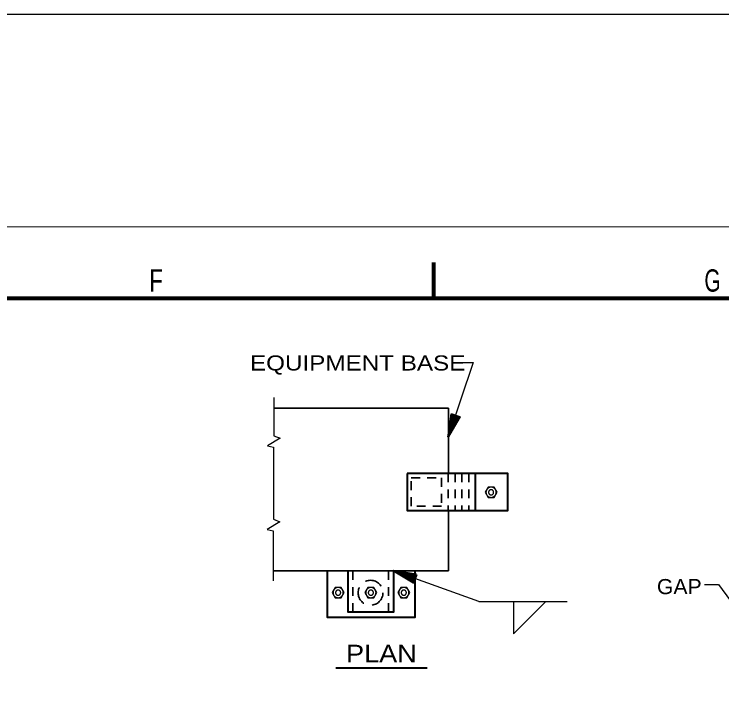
# Model space of a CAD drawing. Extents: x 55 to 190, y 198 to 264.
# Drawn here: x 114.24 to 126.14, y 249.95 to 261.43 of the extents above; entities that cross this region are included whole.
import ezdxf
from ezdxf.enums import TextEntityAlignment as Align

# ---------------------------------------------------------------- set-up
doc = ezdxf.new("R2010")
doc.units = 0
doc.header["$LTSCALE"] = 0.1
doc.linetypes.add('MEDIUM_DASHED', pattern=[4.5, 3, -1.5])
doc.linetypes.add('SHORT_DASHED', pattern=[2.7, 1.5, -1.2])
for name, color, linetype, lineweight in [('1', 7, 'Continuous', 25), ('2', 7, 'Continuous', 40), ('3', 7, 'Continuous', 25)]:
    doc.layers.add(name, color=color, linetype=linetype, lineweight=lineweight)

msp = doc.modelspace()

# ---------------------------------------------------------------- linework, layer by layer
at = {"layer": '1', "lineweight": 80}
msp.add_line((121.2927, 257.2525), (121.2927, 256.6525), dxfattribs=at)
at = {"layer": '1', "lineweight": 13}
msp.add_lwpolyline([(62.4915, 257.8525), (146.5927, 257.8525), (146.5927, 198.4512), (62.4915, 198.4512)], close=True, dxfattribs=at)
at = {"layer": '1', "lineweight": 80}
msp.add_lwpolyline([(65.1915, 256.6525), (145.3927, 256.6525), (145.3927, 199.6512), (65.1915, 199.6512)], close=True, dxfattribs=at)
at = {"layer": '2'}
for p, q in [((121.5389, 254.3221), (121.6058, 254.7029)), ((121.5389, 254.3221), (121.6265, 254.6965)), ((121.5389, 254.3221), (121.6424, 254.6907)), ((121.6593, 254.6854), (121.5389, 254.3221)), ((121.5389, 254.3221), (121.6775, 254.6791)), ((121.5389, 254.3221), (121.7127, 254.6672)), ((121.9919, 253.7091), (121.9919, 253.0871)), ((120.9806, 251.9388), (120.6203, 252.0671)), ((120.6203, 252.0671), (120.9928, 251.9713)), ((120.6203, 252.0671), (120.9616, 251.8856)), ((120.6203, 252.0671), (120.974, 251.9208)), ((120.6203, 252.0671), (120.9865, 251.9554)), ((120.6203, 252.0671), (120.9994, 251.9917)), ((119.6463, 250.437), (121.182, 250.437))]:
    msp.add_line(p, q, dxfattribs=at)
at = {"layer": '2', "linetype": 'SHORT_DASHED', "lineweight": 35}
for p, q in [((121.5381, 253.7091), (121.5381, 253.0871)), ((121.6535, 253.7091), (121.6535, 253.0871)), ((121.7686, 253.7091), (121.7686, 253.0871)), ((121.8874, 253.7091), (121.8874, 253.0871)), ((119.9369, 252.0671), (119.9369, 251.3739)), ((120.5351, 252.0671), (120.5351, 251.3739))]:
    msp.add_line(p, q, dxfattribs=at)
at = {"layer": '2', "lineweight": 35}
for p in [(121.5418, 253.0881), (118.6002, 252.0676)]:
    msp.add_line(p, (121.5418, 252.0676), dxfattribs=at)
at = {"layer": '2', "lineweight": 25}
for q in [(120.6203, 252.0671), (123.5423, 251.5533)]:
    msp.add_line((122.0562, 251.5533), q, dxfattribs=at)
for points in [[(121.6971, 255.5747), (121.9561, 255.5747), (121.5389, 254.3221)], [(118.6071, 254.9844), (118.6071, 254.3428), (118.7139, 254.2999), (118.4999, 254.1713), (118.5999, 254.1499), (118.5999, 253.4646)], [(118.5999, 253.4646), (118.5999, 252.9365), (118.7068, 252.8936), (118.4928, 252.765), (118.5928, 252.7436), (118.5928, 251.9038)], [(125.8499, 251.8406), (126.0854, 251.8406), (127.0143, 250.5714)], [(122.6385, 251.5533), (122.6385, 251.0109), (123.1809, 251.5533)]]:
    msp.add_lwpolyline(points, dxfattribs=at)
at = {"layer": '2', "lineweight": 35}
msp.add_lwpolyline([(118.6068, 254.8042), (121.5418, 254.8042), (121.5418, 253.7056)], dxfattribs=at)
at = {"layer": '2'}
for points in [[(121.5873, 254.709), (121.7326, 254.6603), (121.5389, 254.3221)], [(121.5873, 254.709), (121.5389, 254.3221), (121.6955, 254.6732)], [(119.5008, 252.0663), (119.5008, 251.2929), (120.9828, 251.2929), (120.9828, 252.0663)], [(120.6203, 252.0671), (120.6203, 251.3739), (119.854, 251.3739), (119.854, 252.0671)], [(121.006, 252.0099), (120.9542, 251.866), (120.6203, 252.0671)], [(121.006, 252.0099), (120.6203, 252.0671), (120.9679, 251.9028)]]:
    msp.add_lwpolyline(points, dxfattribs=at)
msp.add_lwpolyline([(120.8497, 253.7091), (120.8497, 253.0871), (122.5411, 253.0871), (122.5411, 253.7091)], close=True, dxfattribs=at)
at = {"layer": '2', "linetype": 'SHORT_DASHED', "lineweight": 35}
msp.add_lwpolyline([(121.4283, 253.6337), (121.4283, 253.158), (120.915, 253.158), (120.915, 253.6337)], close=True, dxfattribs=at)
at = {"layer": '2', "lineweight": 25}
for points in [[(122.3607, 253.3913), (122.3102, 253.4786), (122.2096, 253.4786), (122.1593, 253.3913), (122.2096, 253.3048), (122.3102, 253.3048)], [(122.3451, 253.3807), (122.3464, 253.3969), (122.3451, 253.4019), (122.3445, 253.4077), (122.3438, 253.413), (122.3419, 253.4183), (122.3403, 253.4231), (122.3382, 253.4281), (122.3358, 253.4329), (122.3327, 253.4379), (122.3297, 253.4419), (122.3263, 253.4464), (122.3229, 253.4503), (122.3189, 253.454), (122.3152, 253.458), (122.3104, 253.4612), (122.3065, 253.4644), (122.3017, 253.4673), (122.2967, 253.4694), (122.2916, 253.4715), (122.2864, 253.4734), (122.2816, 253.4752), (122.2758, 253.476), (122.2707, 253.4768), (122.2652, 253.4776), (122.2599, 253.4776), (122.2546, 253.4776), (122.2493, 253.4768), (122.2438, 253.476), (122.2382, 253.4752), (122.2334, 253.4734), (122.2284, 253.4715), (122.2231, 253.4694), (122.2184, 253.4673), (122.2139, 253.4644), (122.2096, 253.4612), (122.2049, 253.458), (122.2014, 253.454), (122.1972, 253.4503), (122.1935, 253.4464), (122.19, 253.4419), (122.1874, 253.4379), (122.1845, 253.4329), (122.1816, 253.4281), (122.1795, 253.4231), (122.1781, 253.4183), (122.1763, 253.413), (122.1755, 253.4077), (122.1747, 253.4019), (122.1739, 253.3969), (122.1739, 253.3913), (122.1739, 253.3863), (122.1747, 253.3807), (122.1755, 253.3752), (122.1763, 253.3699), (122.1781, 253.3649), (122.1795, 253.3598), (122.1816, 253.3548), (122.1845, 253.3495), (122.1874, 253.3453), (122.19, 253.3408), (122.1935, 253.3365), (122.1972, 253.3329), (122.2014, 253.3286), (122.2049, 253.3249), (122.2096, 253.3217), (122.2139, 253.3188), (122.2184, 253.3159), (122.2231, 253.3135), (122.2284, 253.3112), (122.2334, 253.3096), (122.2382, 253.3077), (122.2438, 253.3069), (122.2493, 253.3056), (122.2546, 253.3053), (122.2599, 253.3053), (122.2652, 253.3053), (122.2707, 253.3056), (122.2758, 253.3069), (122.2816, 253.3077), (122.2864, 253.3096), (122.2916, 253.3112), (122.2967, 253.3135), (122.3017, 253.3159), (122.3065, 253.3188), (122.3104, 253.3217), (122.3152, 253.3249), (122.3189, 253.3286), (122.3229, 253.3329), (122.3263, 253.3365), (122.3297, 253.3408), (122.3327, 253.3453), (122.3358, 253.3495), (122.3382, 253.3548), (122.3403, 253.3598), (122.3419, 253.3649), (122.3438, 253.3699), (122.3445, 253.3752)], [(122.3028, 253.3845), (122.303, 253.3929), (122.3028, 253.3956), (122.302, 253.3982), (122.3017, 253.4011), (122.3009, 253.4035), (122.3001, 253.4061), (122.2991, 253.4085), (122.298, 253.4106), (122.2961, 253.4136), (122.2948, 253.4157), (122.2932, 253.4178), (122.2914, 253.4202), (122.2895, 253.4212), (122.2874, 253.4236), (122.2856, 253.4252), (122.2834, 253.4265), (122.2808, 253.4281), (122.2782, 253.4292), (122.2755, 253.4305), (122.2734, 253.431), (122.2707, 253.4318), (122.2684, 253.4326), (122.2652, 253.4329), (122.2628, 253.4331), (122.2599, 253.4331), (122.2572, 253.4331), (122.2543, 253.4329), (122.2519, 253.4326), (122.2488, 253.4318), (122.2461, 253.431), (122.2438, 253.4305), (122.2416, 253.4292), (122.239, 253.4281), (122.2369, 253.4265), (122.2348, 253.4252), (122.2318, 253.4236), (122.2305, 253.4212), (122.2284, 253.4202), (122.2266, 253.4178), (122.225, 253.4157), (122.2231, 253.4136), (122.2223, 253.4106), (122.2207, 253.4085), (122.2194, 253.4061), (122.2189, 253.4035), (122.2178, 253.4011), (122.2173, 253.3982), (122.217, 253.3956), (122.2165, 253.3929), (122.2165, 253.3897), (122.2165, 253.3874), (122.217, 253.3845), (122.2173, 253.3823), (122.2178, 253.3789), (122.2189, 253.3768), (122.2194, 253.3741), (122.2207, 253.3718), (122.2223, 253.3688), (122.2231, 253.3667), (122.225, 253.3649), (122.2266, 253.3625), (122.2284, 253.3606), (122.2305, 253.3583), (122.2318, 253.3572), (122.2348, 253.3553), (122.2369, 253.3538), (122.239, 253.3522), (122.2416, 253.3511), (122.2438, 253.3495), (122.2461, 253.349), (122.2488, 253.3479), (122.2519, 253.3477), (122.2543, 253.3474), (122.2572, 253.3469), (122.2599, 253.3469), (122.2628, 253.3469), (122.2652, 253.3474), (122.2684, 253.3477), (122.2707, 253.3479), (122.2734, 253.349), (122.2755, 253.3495), (122.2782, 253.3511), (122.2808, 253.3522), (122.2834, 253.3538), (122.2856, 253.3553), (122.2874, 253.3572), (122.2895, 253.3583), (122.2914, 253.3606), (122.2932, 253.3625), (122.2948, 253.3649), (122.2961, 253.3667), (122.298, 253.3688), (122.2991, 253.3718), (122.3001, 253.3741), (122.3009, 253.3768), (122.3017, 253.3789), (122.302, 253.3823)], [(119.7876, 251.7036), (119.7371, 251.7909), (119.6366, 251.7909), (119.5863, 251.7036), (119.6366, 251.617), (119.7371, 251.617)], [(119.772, 251.693), (119.7733, 251.7091), (119.772, 251.7141), (119.7715, 251.72), (119.7707, 251.7252), (119.7688, 251.7305), (119.7673, 251.7353), (119.7651, 251.7403), (119.7627, 251.7451), (119.7596, 251.7501), (119.7567, 251.7541), (119.7532, 251.7586), (119.7498, 251.7626), (119.7458, 251.7663), (119.7421, 251.7702), (119.7374, 251.7734), (119.7334, 251.7766), (119.7286, 251.7795), (119.7236, 251.7816), (119.7186, 251.7837), (119.7133, 251.7856), (119.7085, 251.7874), (119.7027, 251.7882), (119.6977, 251.789), (119.6921, 251.7898), (119.6868, 251.7898), (119.6815, 251.7898), (119.6762, 251.789), (119.6707, 251.7882), (119.6651, 251.7874), (119.6604, 251.7856), (119.6553, 251.7837), (119.65, 251.7816), (119.6453, 251.7795), (119.6408, 251.7766), (119.6366, 251.7734), (119.6318, 251.7702), (119.6283, 251.7663), (119.6241, 251.7626), (119.6204, 251.7586), (119.617, 251.7541), (119.6143, 251.7501), (119.6114, 251.7451), (119.6085, 251.7403), (119.6064, 251.7353), (119.6051, 251.7305), (119.6032, 251.7252), (119.6024, 251.72), (119.6016, 251.7141), (119.6008, 251.7091), (119.6008, 251.7036), (119.6008, 251.6985), (119.6016, 251.693), (119.6024, 251.6874), (119.6032, 251.6821), (119.6051, 251.6771), (119.6064, 251.6721), (119.6085, 251.667), (119.6114, 251.6617), (119.6143, 251.6575), (119.617, 251.653), (119.6204, 251.6488), (119.6241, 251.6451), (119.6283, 251.6408), (119.6318, 251.6371), (119.6366, 251.634), (119.6408, 251.631), (119.6453, 251.6281), (119.65, 251.6258), (119.6553, 251.6234), (119.6604, 251.6218), (119.6651, 251.6199), (119.6707, 251.6192), (119.6762, 251.6178), (119.6815, 251.6176), (119.6868, 251.6176), (119.6921, 251.6176), (119.6977, 251.6178), (119.7027, 251.6192), (119.7085, 251.6199), (119.7133, 251.6218), (119.7186, 251.6234), (119.7236, 251.6258), (119.7286, 251.6281), (119.7334, 251.631), (119.7374, 251.634), (119.7421, 251.6371), (119.7458, 251.6408), (119.7498, 251.6451), (119.7532, 251.6488), (119.7567, 251.653), (119.7596, 251.6575), (119.7627, 251.6617), (119.7651, 251.667), (119.7673, 251.6721), (119.7688, 251.6771), (119.7707, 251.6821), (119.7715, 251.6874)], [(120.3382, 251.7036), (120.2877, 251.7909), (120.1871, 251.7909), (120.1369, 251.7036), (120.1871, 251.617), (120.2877, 251.617)], [(120.3226, 251.693), (120.3239, 251.7091), (120.3226, 251.7141), (120.3221, 251.72), (120.3213, 251.7252), (120.3194, 251.7305), (120.3179, 251.7353), (120.3157, 251.7403), (120.3134, 251.7451), (120.3102, 251.7501), (120.3073, 251.7541), (120.3038, 251.7586), (120.3004, 251.7626), (120.2964, 251.7663), (120.2927, 251.7702), (120.2879, 251.7734), (120.284, 251.7766), (120.2792, 251.7795), (120.2742, 251.7816), (120.2692, 251.7837), (120.2639, 251.7856), (120.2591, 251.7874), (120.2533, 251.7882), (120.2483, 251.789), (120.2427, 251.7898), (120.2374, 251.7898), (120.2321, 251.7898), (120.2268, 251.789), (120.2213, 251.7882), (120.2157, 251.7874), (120.211, 251.7856), (120.2059, 251.7837), (120.2006, 251.7816), (120.1959, 251.7795), (120.1914, 251.7766), (120.1871, 251.7734), (120.1824, 251.7702), (120.1789, 251.7663), (120.1747, 251.7626), (120.171, 251.7586), (120.1676, 251.7541), (120.1649, 251.7501), (120.162, 251.7451), (120.1591, 251.7403), (120.157, 251.7353), (120.1557, 251.7305), (120.1538, 251.7252), (120.153, 251.72), (120.1522, 251.7141), (120.1514, 251.7091), (120.1514, 251.7036), (120.1514, 251.6985), (120.1522, 251.693), (120.153, 251.6874), (120.1538, 251.6821), (120.1557, 251.6771), (120.157, 251.6721), (120.1591, 251.667), (120.162, 251.6617), (120.1649, 251.6575), (120.1676, 251.653), (120.171, 251.6488), (120.1747, 251.6451), (120.1789, 251.6408), (120.1824, 251.6371), (120.1871, 251.634), (120.1914, 251.631), (120.1959, 251.6281), (120.2006, 251.6258), (120.2059, 251.6234), (120.211, 251.6218), (120.2157, 251.6199), (120.2213, 251.6192), (120.2268, 251.6178), (120.2321, 251.6176), (120.2374, 251.6176), (120.2427, 251.6176), (120.2483, 251.6178), (120.2533, 251.6192), (120.2591, 251.6199), (120.2639, 251.6218), (120.2692, 251.6234), (120.2742, 251.6258), (120.2792, 251.6281), (120.284, 251.631), (120.2879, 251.634), (120.2927, 251.6371), (120.2964, 251.6408), (120.3004, 251.6451), (120.3038, 251.6488), (120.3073, 251.653), (120.3102, 251.6575), (120.3134, 251.6617), (120.3157, 251.667), (120.3179, 251.6721), (120.3194, 251.6771), (120.3213, 251.6821), (120.3221, 251.6874)], [(120.8925, 251.7036), (120.842, 251.7909), (120.7415, 251.7909), (120.6912, 251.7036), (120.7415, 251.617), (120.842, 251.617)], [(120.8769, 251.693), (120.8782, 251.7091), (120.8769, 251.7141), (120.8764, 251.72), (120.8756, 251.7252), (120.8737, 251.7305), (120.8722, 251.7353), (120.87, 251.7403), (120.8677, 251.7451), (120.8645, 251.7501), (120.8616, 251.7541), (120.8581, 251.7586), (120.8547, 251.7626), (120.8507, 251.7663), (120.847, 251.7702), (120.8422, 251.7734), (120.8383, 251.7766), (120.8335, 251.7795), (120.8285, 251.7816), (120.8235, 251.7837), (120.8182, 251.7856), (120.8134, 251.7874), (120.8076, 251.7882), (120.8026, 251.789), (120.797, 251.7898), (120.7917, 251.7898), (120.7864, 251.7898), (120.7811, 251.789), (120.7756, 251.7882), (120.77, 251.7874), (120.7653, 251.7856), (120.7602, 251.7837), (120.7549, 251.7816), (120.7502, 251.7795), (120.7457, 251.7766), (120.7415, 251.7734), (120.7367, 251.7702), (120.7332, 251.7663), (120.729, 251.7626), (120.7253, 251.7586), (120.7219, 251.7541), (120.7192, 251.7501), (120.7163, 251.7451), (120.7134, 251.7403), (120.7113, 251.7353), (120.71, 251.7305), (120.7081, 251.7252), (120.7073, 251.72), (120.7065, 251.7141), (120.7057, 251.7091), (120.7057, 251.7036), (120.7057, 251.6985), (120.7065, 251.693), (120.7073, 251.6874), (120.7081, 251.6821), (120.71, 251.6771), (120.7113, 251.6721), (120.7134, 251.667), (120.7163, 251.6617), (120.7192, 251.6575), (120.7219, 251.653), (120.7253, 251.6488), (120.729, 251.6451), (120.7332, 251.6408), (120.7367, 251.6371), (120.7415, 251.634), (120.7457, 251.631), (120.7502, 251.6281), (120.7549, 251.6258), (120.7602, 251.6234), (120.7653, 251.6218), (120.77, 251.6199), (120.7756, 251.6192), (120.7811, 251.6178), (120.7864, 251.6176), (120.7917, 251.6176), (120.797, 251.6176), (120.8026, 251.6178), (120.8076, 251.6192), (120.8134, 251.6199), (120.8182, 251.6218), (120.8235, 251.6234), (120.8285, 251.6258), (120.8335, 251.6281), (120.8383, 251.631), (120.8422, 251.634), (120.847, 251.6371), (120.8507, 251.6408), (120.8547, 251.6451), (120.8581, 251.6488), (120.8616, 251.653), (120.8645, 251.6575), (120.8677, 251.6617), (120.87, 251.667), (120.8722, 251.6721), (120.8737, 251.6771), (120.8756, 251.6821), (120.8764, 251.6874)], [(119.7297, 251.6967), (119.7299, 251.7051), (119.7297, 251.7078), (119.7289, 251.7104), (119.7286, 251.7133), (119.7278, 251.7157), (119.727, 251.7184), (119.726, 251.7208), (119.7249, 251.7229), (119.7231, 251.7258), (119.7217, 251.7279), (119.7202, 251.73), (119.7183, 251.7324), (119.7164, 251.7334), (119.7143, 251.7358), (119.7125, 251.7374), (119.7104, 251.7387), (119.7077, 251.7403), (119.7051, 251.7414), (119.7024, 251.7427), (119.7003, 251.7432), (119.6977, 251.744), (119.6953, 251.7448), (119.6921, 251.7451), (119.6897, 251.7454), (119.6868, 251.7454), (119.6842, 251.7454), (119.6813, 251.7451), (119.6789, 251.7448), (119.6757, 251.744), (119.6731, 251.7432), (119.6707, 251.7427), (119.6686, 251.7414), (119.6659, 251.7403), (119.6638, 251.7387), (119.6617, 251.7374), (119.6588, 251.7358), (119.6575, 251.7334), (119.6553, 251.7324), (119.6535, 251.73), (119.6519, 251.7279), (119.65, 251.7258), (119.6493, 251.7229), (119.6477, 251.7208), (119.6463, 251.7184), (119.6458, 251.7157), (119.6448, 251.7133), (119.6442, 251.7104), (119.6439, 251.7078), (119.6434, 251.7051), (119.6434, 251.702), (119.6434, 251.6996), (119.6439, 251.6967), (119.6442, 251.6946), (119.6448, 251.6911), (119.6458, 251.689), (119.6463, 251.6863), (119.6477, 251.684), (119.6493, 251.6811), (119.65, 251.6789), (119.6519, 251.6771), (119.6535, 251.6747), (119.6553, 251.6729), (119.6575, 251.6705), (119.6588, 251.6694), (119.6617, 251.6676), (119.6638, 251.666), (119.6659, 251.6644), (119.6686, 251.6633), (119.6707, 251.6617), (119.6731, 251.6612), (119.6757, 251.6601), (119.6789, 251.6599), (119.6813, 251.6596), (119.6842, 251.6591), (119.6868, 251.6591), (119.6897, 251.6591), (119.6921, 251.6596), (119.6953, 251.6599), (119.6977, 251.6601), (119.7003, 251.6612), (119.7024, 251.6617), (119.7051, 251.6633), (119.7077, 251.6644), (119.7104, 251.666), (119.7125, 251.6676), (119.7143, 251.6694), (119.7164, 251.6705), (119.7183, 251.6729), (119.7202, 251.6747), (119.7217, 251.6771), (119.7231, 251.6789), (119.7249, 251.6811), (119.726, 251.684), (119.727, 251.6863), (119.7278, 251.689), (119.7286, 251.6911), (119.7289, 251.6946)], [(120.2803, 251.6967), (120.2805, 251.7051), (120.2803, 251.7078), (120.2795, 251.7104), (120.2792, 251.7133), (120.2784, 251.7157), (120.2776, 251.7184), (120.2766, 251.7208), (120.2755, 251.7229), (120.2737, 251.7258), (120.2723, 251.7279), (120.2707, 251.73), (120.2689, 251.7324), (120.2671, 251.7334), (120.2649, 251.7358), (120.2631, 251.7374), (120.261, 251.7387), (120.2583, 251.7403), (120.2557, 251.7414), (120.253, 251.7427), (120.2509, 251.7432), (120.2483, 251.744), (120.2459, 251.7448), (120.2427, 251.7451), (120.2403, 251.7454), (120.2374, 251.7454), (120.2348, 251.7454), (120.2319, 251.7451), (120.2295, 251.7448), (120.2263, 251.744), (120.2236, 251.7432), (120.2213, 251.7427), (120.2192, 251.7414), (120.2165, 251.7403), (120.2144, 251.7387), (120.2123, 251.7374), (120.2094, 251.7358), (120.2081, 251.7334), (120.2059, 251.7324), (120.2041, 251.73), (120.2025, 251.7279), (120.2006, 251.7258), (120.1998, 251.7229), (120.1983, 251.7208), (120.1969, 251.7184), (120.1964, 251.7157), (120.1953, 251.7133), (120.1948, 251.7104), (120.1946, 251.7078), (120.194, 251.7051), (120.194, 251.702), (120.194, 251.6996), (120.1946, 251.6967), (120.1948, 251.6946), (120.1953, 251.6911), (120.1964, 251.689), (120.1969, 251.6863), (120.1983, 251.684), (120.1998, 251.6811), (120.2006, 251.6789), (120.2025, 251.6771), (120.2041, 251.6747), (120.2059, 251.6729), (120.2081, 251.6705), (120.2094, 251.6694), (120.2123, 251.6676), (120.2144, 251.666), (120.2165, 251.6644), (120.2192, 251.6633), (120.2213, 251.6617), (120.2236, 251.6612), (120.2263, 251.6601), (120.2295, 251.6599), (120.2319, 251.6596), (120.2348, 251.6591), (120.2374, 251.6591), (120.2403, 251.6591), (120.2427, 251.6596), (120.2459, 251.6599), (120.2483, 251.6601), (120.2509, 251.6612), (120.253, 251.6617), (120.2557, 251.6633), (120.2583, 251.6644), (120.261, 251.666), (120.2631, 251.6676), (120.2649, 251.6694), (120.2671, 251.6705), (120.2689, 251.6729), (120.2707, 251.6747), (120.2723, 251.6771), (120.2737, 251.6789), (120.2755, 251.6811), (120.2766, 251.684), (120.2776, 251.6863), (120.2784, 251.689), (120.2792, 251.6911), (120.2795, 251.6946)], [(120.8346, 251.6967), (120.8348, 251.7051), (120.8346, 251.7078), (120.8338, 251.7104), (120.8335, 251.7133), (120.8327, 251.7157), (120.8319, 251.7184), (120.8309, 251.7208), (120.8298, 251.7229), (120.828, 251.7258), (120.8266, 251.7279), (120.8251, 251.73), (120.8232, 251.7324), (120.8214, 251.7334), (120.8192, 251.7358), (120.8174, 251.7374), (120.8153, 251.7387), (120.8126, 251.7403), (120.81, 251.7414), (120.8073, 251.7427), (120.8052, 251.7432), (120.8026, 251.744), (120.8002, 251.7448), (120.797, 251.7451), (120.7946, 251.7454), (120.7917, 251.7454), (120.7891, 251.7454), (120.7862, 251.7451), (120.7838, 251.7448), (120.7806, 251.744), (120.7779, 251.7432), (120.7756, 251.7427), (120.7735, 251.7414), (120.7708, 251.7403), (120.7687, 251.7387), (120.7666, 251.7374), (120.7637, 251.7358), (120.7624, 251.7334), (120.7602, 251.7324), (120.7584, 251.73), (120.7568, 251.7279), (120.7549, 251.7258), (120.7542, 251.7229), (120.7526, 251.7208), (120.7512, 251.7184), (120.7507, 251.7157), (120.7496, 251.7133), (120.7491, 251.7104), (120.7488, 251.7078), (120.7483, 251.7051), (120.7483, 251.702), (120.7483, 251.6996), (120.7488, 251.6967), (120.7491, 251.6946), (120.7496, 251.6911), (120.7507, 251.689), (120.7512, 251.6863), (120.7526, 251.684), (120.7542, 251.6811), (120.7549, 251.6789), (120.7568, 251.6771), (120.7584, 251.6747), (120.7602, 251.6729), (120.7624, 251.6705), (120.7637, 251.6694), (120.7666, 251.6676), (120.7687, 251.666), (120.7708, 251.6644), (120.7735, 251.6633), (120.7756, 251.6617), (120.7779, 251.6612), (120.7806, 251.6601), (120.7838, 251.6599), (120.7862, 251.6596), (120.7891, 251.6591), (120.7917, 251.6591), (120.7946, 251.6591), (120.797, 251.6596), (120.8002, 251.6599), (120.8026, 251.6601), (120.8052, 251.6612), (120.8073, 251.6617), (120.81, 251.6633), (120.8126, 251.6644), (120.8153, 251.666), (120.8174, 251.6676), (120.8192, 251.6694), (120.8214, 251.6705), (120.8232, 251.6729), (120.8251, 251.6747), (120.8266, 251.6771), (120.828, 251.6789), (120.8298, 251.6811), (120.8309, 251.684), (120.8319, 251.6863), (120.8327, 251.689), (120.8335, 251.6911), (120.8338, 251.6946)]]:
    msp.add_lwpolyline(points, close=True, dxfattribs=at)
at = {"layer": '2', "linetype": 'MEDIUM_DASHED', "lineweight": 35}
msp.add_circle((120.2319, 251.7014), 0.2092, dxfattribs=at)
at = {"layer": '3'}
msp.add_line((62.4915, 261.4312), (146.5927, 261.4312), dxfattribs=at)

# ---------------------------------------------------------------- texts
at = {"layer": '1'}
for s, width, p in [('G', 0.7, (125.9843, 256.765)), ('F', 0.75, (116.6254, 256.765))]:
    msp.add_text(s, height=0.375, dxfattribs=dict(at, width=width)).set_placement(p, align=Align.CENTER)
at = {"layer": '2'}
for s, width, p in [('EQUIPMENT BASE', 1.2, (118.2038, 255.4387)), ('GAP', 1.05, (125.0495, 251.6779))]:
    msp.add_text(s, height=0.254, dxfattribs=dict(at, width=width)).set_placement(p)
at = {"layer": '2', "width": 1.15}
msp.add_text('PLAN', height=0.2963, dxfattribs=at).set_placement((120.4149, 250.5299), align=Align.CENTER)

doc.saveas('drawing.dxf')
